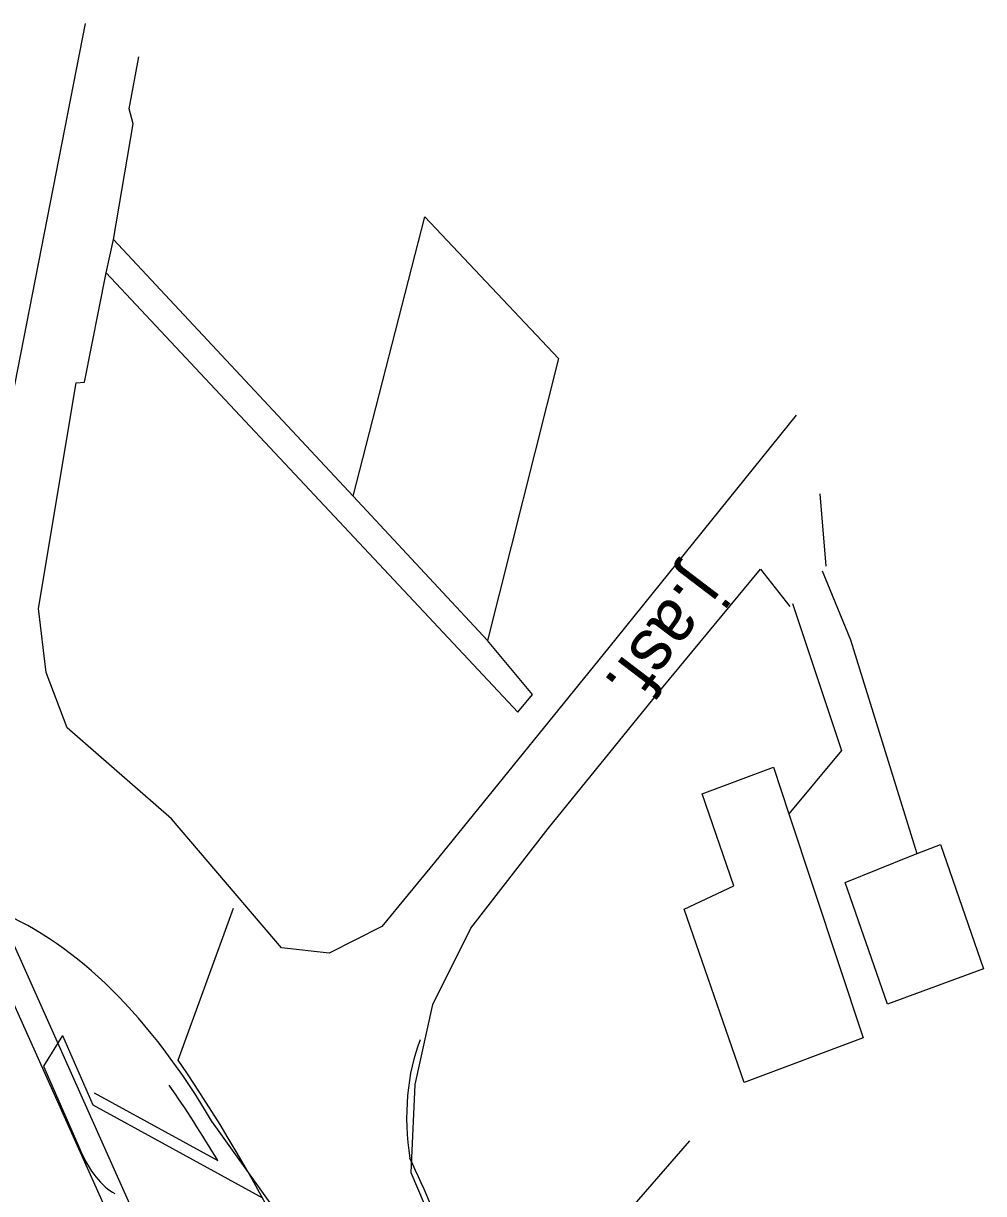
# Model space of a CAD drawing. Extents: x 6541740 to 6566395, y 5525066 to 5530361.
# Drawn here: x 6554145.9 to 6554164.58, y 5525336.42 to 5525359.19 of the extents above; entities that cross this region are included whole.
import ezdxf

# ---------------------------------------------------------------- set-up
doc = ezdxf.new("R2010")
doc.units = 0
for name, color, linetype in [('ps_wymiarowanie', 7, 'Continuous'), ('TOR_PS_OPIS_T-symbole geometrii', 7, 'Continuous'), ('TOR_PS_T-wypelnienia', 7, 'Continuous')]:
    doc.layers.add(name, color=color, linetype=linetype)

msp = doc.modelspace()

# ---------------------------------------------------------------- linework, layer by layer
at = {"layer": 'ps_wymiarowanie'}
for p, q in [((6554152.315, 5525349.994), (6554153.708, 5525355.427)), ((6554153.708, 5525355.427), (6554156.307, 5525352.675)), ((6554156.307, 5525352.675), (6554154.928, 5525347.182)), ((6554154.928, 5525347.182), (6554152.315, 5525349.994))]:
    msp.add_line(p, q, dxfattribs=at)
for points in [[(6554162.233, 5525339.451), (6554159.918, 5525338.583), (6554158.751, 5525341.954), (6554159.72, 5525342.408), (6554159.103, 5525344.199), (6554160.492, 5525344.718), (6554160.792, 5525343.811)], [(6554164.577, 5525340.794), (6554162.708, 5525340.104), (6554161.884, 5525342.475), (6554163.171, 5525342.992), (6554163.737, 5525343.215)]]:
    msp.add_lwpolyline(points, close=True, dxfattribs=at)
at = {"layer": 'TOR_PS_OPIS_T-symbole geometrii'}
for p, q in [((6554148.91, 5525339.013), (6554149.984, 5525341.975)), ((6554146.661, 5525339.499), (6554146.29, 5525338.898)), ((6554146.661, 5525339.499), (6554147.253, 5525338.147)), ((6554146.29, 5525338.898), (6554147.003, 5525337.269)), ((6554147.278, 5525338.383), (6554149.682, 5525337.063)), ((6554147.253, 5525338.147), (6554150.549, 5525336.338))]:
    msp.add_line(p, q, dxfattribs=at)
for centre, major_axis, start_param, end_param in [((6554154.673, 5525337.707), (-0.139, 2.569), 0.819706, 1.778774), ((6554139.689, 5525313.568), (-1.756, 32.37), 4.824583, 5.588672), ((6554139.689, 5525313.568), (-1.722, 31.758), 5.517095, 5.588672), ((6554147.931, 5525338.771), (0.133, -2.447), 5.345473, 5.976121), ((6554139.863, 5525313.698), (-1.993, 36.749), 5.240005, 5.375002)]:
    msp.add_ellipse(centre, major_axis=major_axis, ratio=0.510219, start_param=start_param, end_param=end_param, dxfattribs=at)
at = {"layer": 'TOR_PS_T-wypelnienia'}
for p, q in [((6554147.099, 5525359.195), (6554145.673, 5525351.897)), ((6554147.958, 5525357.534), (6554148.147, 5525358.542)), ((6554148.036, 5525357.237), (6554147.958, 5525357.534)), ((6554147.652, 5525354.986), (6554148.036, 5525357.237)), ((6554147.512, 5525354.343), (6554147.652, 5525354.986)), ((6554152.315, 5525349.994), (6554147.652, 5525354.986)), ((6554147.09, 5525352.209), (6554147.512, 5525354.343)), ((6554147.512, 5525354.343), (6554155.515, 5525345.788)), ((6554146.193, 5525347.804), (6554146.925, 5525352.2)), ((6554146.925, 5525352.2), (6554147.09, 5525352.209)), ((6554160.933, 5525351.568), (6554157.287, 5525347.045)), ((6554152.315, 5525349.994), (6554154.928, 5525347.182)), ((6554161.518, 5525348.63), (6554161.399, 5525350.04)), ((6554158.314, 5525346.245), (6554160.239, 5525348.57)), ((6554160.239, 5525348.57), (6554160.809, 5525347.847)), ((6554146.341, 5525346.559), (6554146.193, 5525347.804)), ((6554155.806, 5525346.132), (6554154.928, 5525347.182)), ((6554157.287, 5525347.045), (6554154.26, 5525343.312)), ((6554146.75, 5525345.482), (6554146.341, 5525346.559)), ((6554155.515, 5525345.788), (6554155.806, 5525346.132)), ((6554156.108, 5525343.523), (6554158.314, 5525346.245)), ((6554148.778, 5525343.713), (6554146.75, 5525345.482)), ((6554150.921, 5525341.204), (6554148.778, 5525343.713)), ((6554154.605, 5525341.586), (6554156.108, 5525343.523)), ((6554154.26, 5525343.312), (6554153.895, 5525342.862)), ((6554153.895, 5525342.862), (6554152.871, 5525341.616)), ((6554149.476, 5525332.847), (6554145.42, 5525341.912)), ((6554152.871, 5525341.616), (6554151.846, 5525341.1)), ((6554153.867, 5525340.1), (6554154.605, 5525341.586)), ((6554145.186, 5525341.277), (6554149.47, 5525331.726)), ((6554151.846, 5525341.1), (6554150.921, 5525341.204)), ((6554153.518, 5525338.54), (6554153.867, 5525340.1)), ((6554153.444, 5525336.824), (6554153.518, 5525338.54)), ((6554150.702, 5525336.241), (6554149.577, 5525337.806)), ((6554158.86, 5525337.443), (6554156.179, 5525334.37)), ((6554153.884, 5525335.796), (6554153.444, 5525336.824))]:
    msp.add_line(p, q, dxfattribs=at)
for points in [[(6554161.436, 5525348.54), (6554161.987, 5525347.197), (6554163.281, 5525343.036)], [(6554160.863, 5525347.907), (6554161.816, 5525345.046), (6554160.792, 5525343.811)]]:
    msp.add_lwpolyline(points, dxfattribs=at)
msp.add_ellipse((6554144.246, 5525325.64), major_axis=(-0.903, 16.653), ratio=0.510219, start_param=5.503424, end_param=6.03937, dxfattribs=at)

# ---------------------------------------------------------------- texts
msp.add_text('j.asf.', height=1, rotation=232.7014, dxfattribs=at).set_placement((6554158.869, 5525348.617))

doc.saveas('drawing.dxf')
